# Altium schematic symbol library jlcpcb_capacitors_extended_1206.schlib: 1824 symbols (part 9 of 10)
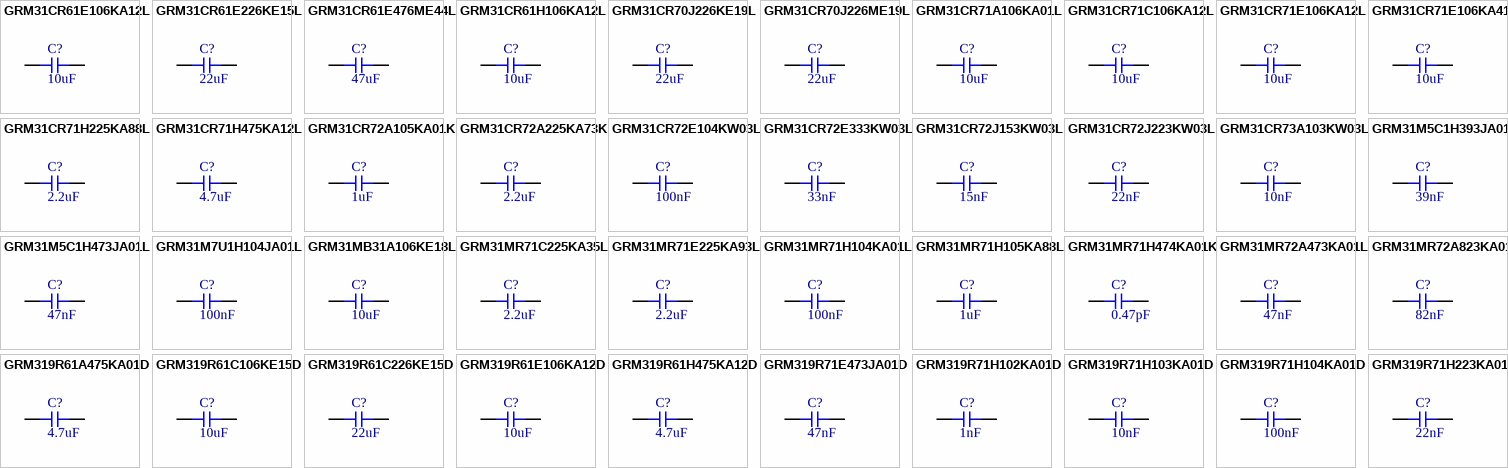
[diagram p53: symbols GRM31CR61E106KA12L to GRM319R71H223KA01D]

## GRM31CR72E333KW03L
designator C?  Capacitance: 33nF  (hidden comment: *)
Capacitor, Ceramic (MLCC), 33nF, ±10%, 250V, X7R, ±10%, SMD 1206; Manufacturer: Murata Electronics; Manufacturer Part Number: GRM31CR72E333KW03L
footprint CAP-1206 (1206 (3216M) Capacitor)
pins: 1, 2

## GRM31CR72J153KW03L
designator C?  Capacitance: 15nF  (hidden comment: *)
Capacitor, Ceramic (MLCC), 15nF, ±10%, 630V, X7R, ±10%, SMD 1206; Manufacturer: Murata Electronics; Manufacturer Part Number: GRM31CR72J153KW03L
footprint CAP-1206 (1206 (3216M) Capacitor)
pins: 1, 2

## GRM31CR72J223KW03L
designator C?  Capacitance: 22nF  (hidden comment: *)
Capacitor, Ceramic (MLCC), 22nF, ±10%, 630V, X7R, ±10%, SMD 1206; Manufacturer: Murata Electronics; Manufacturer Part Number: GRM31CR72J223KW03L
footprint CAP-1206 (1206 (3216M) Capacitor)
pins: 1, 2

## GRM31CR73A103KW03L
designator C?  Capacitance: 10nF  (hidden comment: *)
Capacitor, Ceramic (MLCC), 10nF, ±10%, 1kV, X7R, ±10%, SMD 1206; Manufacturer: Murata Electronics; Manufacturer Part Number: GRM31CR73A103KW03L
footprint CAP-1206 (1206 (3216M) Capacitor)
pins: 1, 2

## GRM31M5C1H393JA01L
designator C?  Capacitance: 39nF  (hidden comment: *)
Capacitor, Ceramic (MLCC), 39nF, ±5%, ±5%, SMD 1206; Manufacturer: Murata Electronics; Manufacturer Part Number: GRM31M5C1H393JA01L
footprint CAP-1206 (1206 (3216M) Capacitor)
pins: 1, 2

## GRM31M5C1H473JA01L
designator C?  Capacitance: 47nF  (hidden comment: *)
Capacitor, Ceramic (MLCC), 47nF, ±5%, 50V, C0G, ±5%, SMD 1206; Manufacturer: Murata Electronics; Manufacturer Part Number: GRM31M5C1H473JA01L
footprint CAP-1206 (1206 (3216M) Capacitor)
pins: 1, 2

## GRM31M7U1H104JA01L
designator C?  Capacitance: 100nF  (hidden comment: *)
Capacitor, Ceramic (MLCC), 100nF, ±5%, 50V, U2J, ±5%, SMD 1206; Manufacturer: Murata Electronics; Manufacturer Part Number: GRM31M7U1H104JA01L
footprint CAP-1206 (1206 (3216M) Capacitor)
pins: 1, 2

## GRM31MB31A106KE18L
designator C?  Capacitance: 10uF  (hidden comment: *)
Capacitor, Ceramic (MLCC), 10uF, ±10%, 10V, B, ±10%, SMD 1206; Manufacturer: Murata Electronics; Manufacturer Part Number: GRM31MB31A106KE18L
footprint CAP-1206 (1206 (3216M) Capacitor)
pins: 1, 2

## GRM31MR71C225KA35L
designator C?  Capacitance: 2.2uF  (hidden comment: *)
Capacitor, Ceramic (MLCC), 2.2uF, ±10%, 16V, X7R, ±10%, SMD 1206; Manufacturer: Murata Electronics; Manufacturer Part Number: GRM31MR71C225KA35L
footprint CAP-1206 (1206 (3216M) Capacitor)
pins: 1, 2

## GRM31MR71E225KA93L
designator C?  Capacitance: 2.2uF  (hidden comment: *)
Capacitor, Ceramic (MLCC), 2.2uF, ±10%, 25V, X7R, ±10%, SMD 1206; Manufacturer: Murata Electronics; Manufacturer Part Number: GRM31MR71E225KA93L
footprint CAP-1206 (1206 (3216M) Capacitor)
pins: 1, 2

## GRM31MR71H104KA01L
designator C?  Capacitance: 100nF  (hidden comment: *)
Capacitor, Ceramic (MLCC), 100nF, ±10%, ±10%, SMD 1206; Manufacturer: Murata Electronics; Manufacturer Part Number: GRM31MR71H104KA01L
footprint CAP-1206 (1206 (3216M) Capacitor)
pins: 1, 2

## GRM31MR71H105KA88L
designator C?  Capacitance: 1uF  (hidden comment: *)
Capacitor, Ceramic (MLCC), 1uF, ±10%, 50V, X7R, ±10%, SMD 1206; Manufacturer: Murata Electronics; Manufacturer Part Number: GRM31MR71H105KA88L
footprint CAP-1206 (1206 (3216M) Capacitor)
pins: 1, 2

## GRM31MR71H474KA01K
designator C?  Capacitance: 0.47pF  (hidden comment: *)
Capacitor, Ceramic (MLCC), 0.47pF, ±10%, 50V, X7R, ±10%, SMD 1206; Manufacturer: Murata Electronics; Manufacturer Part Number: GRM31MR71H474KA01K
footprint CAP-1206 (1206 (3216M) Capacitor)
pins: 1, 2

## GRM31MR72A473KA01L
designator C?  Capacitance: 47nF  (hidden comment: *)
Capacitor, Ceramic (MLCC), 47nF, ±10%, 100V, X7R, ±10%, SMD 1206; Manufacturer: Murata Electronics; Manufacturer Part Number: GRM31MR72A473KA01L
footprint CAP-1206 (1206 (3216M) Capacitor)
pins: 1, 2

## GRM31MR72A823KA01L
designator C?  Capacitance: 82nF  (hidden comment: *)
Capacitor, Ceramic (MLCC), 82nF, ±10%, 100V, X7R, ±10%, SMD 1206; Manufacturer: Murata Electronics; Manufacturer Part Number: GRM31MR72A823KA01L
footprint CAP-1206 (1206 (3216M) Capacitor)
pins: 1, 2

## GRM319R61A475KA01D
designator C?  Capacitance: 4.7uF  (hidden comment: *)
Capacitor, Ceramic (MLCC), 4.7uF, ±10%, 10V, X5R, ±10%, SMD 1206; Manufacturer: Murata Electronics; Manufacturer Part Number: GRM319R61A475KA01D
footprint CAP-1206 (1206 (3216M) Capacitor)
pins: 1, 2

## GRM319R61C106KE15D
designator C?  Capacitance: 10uF  (hidden comment: *)
Capacitor, Ceramic (MLCC), 10uF, ±10%, 16V, X5R, ±10%, SMD 1206; Manufacturer: Murata Electronics; Manufacturer Part Number: GRM319R61C106KE15D
footprint CAP-1206 (1206 (3216M) Capacitor)
pins: 1, 2

## GRM319R61C226KE15D
designator C?  Capacitance: 22uF  (hidden comment: *)
Capacitor, Ceramic (MLCC), 22uF, ±10%, 16V, X5R, ±10%, SMD 1206; Manufacturer: Murata Electronics; Manufacturer Part Number: GRM319R61C226KE15D
footprint CAP-1206 (1206 (3216M) Capacitor)
pins: 1, 2

## GRM319R61E106KA12D
designator C?  Capacitance: 10uF  (hidden comment: *)
Capacitor, Ceramic (MLCC), 10uF, ±10%, 25V, X5R, ±10%, SMD 1206; Manufacturer: Murata Electronics; Manufacturer Part Number: GRM319R61E106KA12D
footprint CAP-1206 (1206 (3216M) Capacitor)
pins: 1, 2

## GRM319R61H475KA12D
designator C?  Capacitance: 4.7uF  (hidden comment: *)
Capacitor, Ceramic (MLCC), 4.7uF, ±10%, 50V, X5R, ±10%, SMD 1206; Manufacturer: Murata Electronics; Manufacturer Part Number: GRM319R61H475KA12D
footprint CAP-1206 (1206 (3216M) Capacitor)
pins: 1, 2

## GRM319R71E473JA01D
designator C?  Capacitance: 47nF  (hidden comment: *)
Capacitor, Ceramic (MLCC), 47nF, ±5%, 25V, X7R, ±5%, SMD 1206; Manufacturer: Murata Electronics; Manufacturer Part Number: GRM319R71E473JA01D
footprint CAP-1206 (1206 (3216M) Capacitor)
pins: 1, 2

## GRM319R71H102KA01D
designator C?  Capacitance: 1nF  (hidden comment: *)
Capacitor, Ceramic (MLCC), 1nF, ±10%, 50V, X7R, ±10%, SMD 1206; Manufacturer: Murata Electronics; Manufacturer Part Number: GRM319R71H102KA01D
footprint CAP-1206 (1206 (3216M) Capacitor)
pins: 1, 2

## GRM319R71H103KA01D
designator C?  Capacitance: 10nF  (hidden comment: *)
Capacitor, Ceramic (MLCC), 10nF, ±10%, 50V, X7R, ±10%, SMD 1206; Manufacturer: Murata Electronics; Manufacturer Part Number: GRM319R71H103KA01D
footprint CAP-1206 (1206 (3216M) Capacitor)
pins: 1, 2

## GRM319R71H104KA01D
designator C?  Capacitance: 100nF  (hidden comment: *)
Capacitor, Ceramic (MLCC), 100nF, ±10%, 50V, X7R, ±10%, SMD 1206; Manufacturer: Murata Electronics; Manufacturer Part Number: GRM319R71H104KA01D
footprint CAP-1206 (1206 (3216M) Capacitor)
pins: 1, 2

## GRM319R71H223KA01D
designator C?  Capacitance: 22nF  (hidden comment: *)
Capacitor, Ceramic (MLCC), 22nF, ±10%, 50V, X7R, ±10%, SMD 1206; Manufacturer: Murata Electronics; Manufacturer Part Number: GRM319R71H223KA01D
footprint CAP-1206 (1206 (3216M) Capacitor)
pins: 1, 2

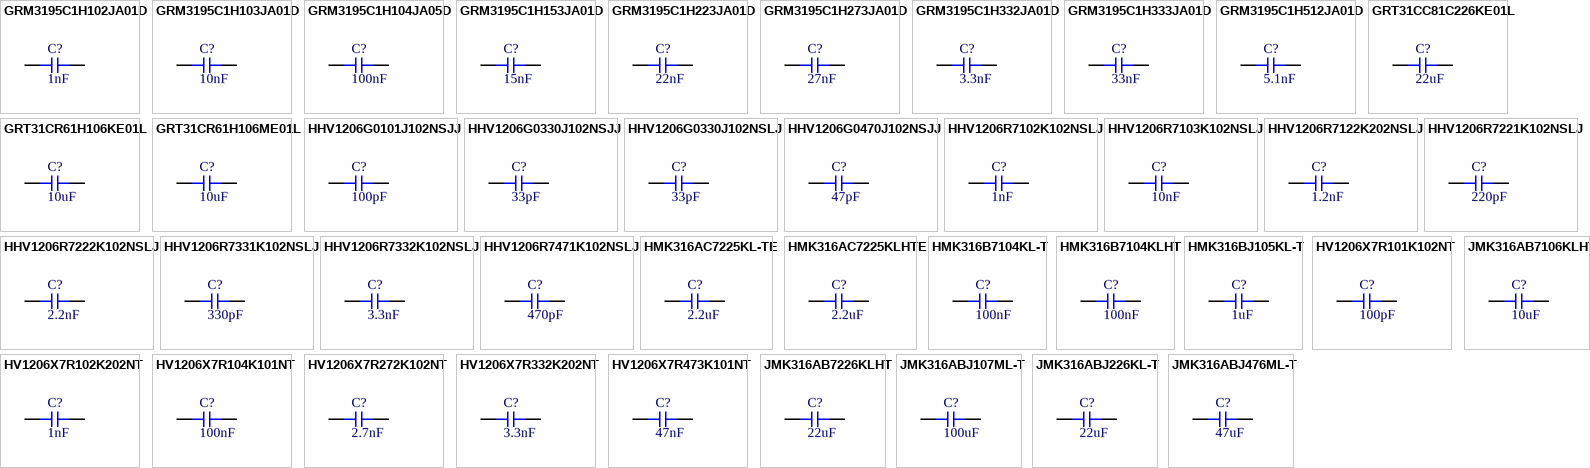
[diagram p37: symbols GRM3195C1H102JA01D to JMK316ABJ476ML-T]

## GRM3195C1H102JA01D
designator C?  Capacitance: 1nF  (hidden comment: *)
Capacitor, Ceramic (MLCC), 1nF, ±5%, 50V, C0G, ±5%, SMD 1206; Manufacturer: Murata Electronics; Manufacturer Part Number: GRM3195C1H102JA01D
footprint CAP-1206 (1206 (3216M) Capacitor)
pins: 1, 2

## GRM3195C1H103JA01D
designator C?  Capacitance: 10nF  (hidden comment: *)
Capacitor, Ceramic (MLCC), 10nF, ±5%, 50V, C0G, ±5%, SMD 1206; Manufacturer: Murata Electronics; Manufacturer Part Number: GRM3195C1H103JA01D
footprint CAP-1206 (1206 (3216M) Capacitor)
pins: 1, 2

## GRM3195C1H104JA05D
designator C?  Capacitance: 100nF  (hidden comment: *)
Capacitor, Ceramic (MLCC), 100nF, ±5%, 50V, C0G, ±5%, SMD 1206; Manufacturer: Murata Electronics; Manufacturer Part Number: GRM3195C1H104JA05D
footprint CAP-1206 (1206 (3216M) Capacitor)
pins: 1, 2

## GRM3195C1H153JA01D
designator C?  Capacitance: 15nF  (hidden comment: *)
Capacitor, Ceramic (MLCC), 15nF, ±5%, 50V, C0G, ±5%, SMD 1206; Manufacturer: Murata Electronics; Manufacturer Part Number: GRM3195C1H153JA01D
footprint CAP-1206 (1206 (3216M) Capacitor)
pins: 1, 2

## GRM3195C1H223JA01D
designator C?  Capacitance: 22nF  (hidden comment: *)
Capacitor, Ceramic (MLCC), 22nF, ±5%, 50V, C0G, ±5%, SMD 1206; Manufacturer: Murata Electronics; Manufacturer Part Number: GRM3195C1H223JA01D
footprint CAP-1206 (1206 (3216M) Capacitor)
pins: 1, 2

## GRM3195C1H273JA01D
designator C?  Capacitance: 27nF  (hidden comment: *)
Capacitor, Ceramic (MLCC), 27nF, ±5%, 50V, C0G, ±5%, SMD 1206; Manufacturer: Murata Electronics; Manufacturer Part Number: GRM3195C1H273JA01D
footprint CAP-1206 (1206 (3216M) Capacitor)
pins: 1, 2

## GRM3195C1H332JA01D
designator C?  Capacitance: 3.3nF  (hidden comment: *)
Capacitor, Ceramic (MLCC), 3.3nF, ±5%, 50V, C0G, ±5%, SMD 1206; Manufacturer: Murata Electronics; Manufacturer Part Number: GRM3195C1H332JA01D
footprint CAP-1206 (1206 (3216M) Capacitor)
pins: 1, 2

## GRM3195C1H333JA01D
designator C?  Capacitance: 33nF  (hidden comment: *)
Capacitor, Ceramic (MLCC), 33nF, ±5%, 50V, C0G, ±5%, SMD 1206; Manufacturer: Murata Electronics; Manufacturer Part Number: GRM3195C1H333JA01D
footprint CAP-1206 (1206 (3216M) Capacitor)
pins: 1, 2

## GRM3195C1H512JA01D
designator C?  Capacitance: 5.1nF  (hidden comment: *)
Capacitor, Ceramic (MLCC), 5.1nF, ±5%, 50V, C0G, ±5%, SMD 1206; Manufacturer: Murata Electronics; Manufacturer Part Number: GRM3195C1H512JA01D
footprint CAP-1206 (1206 (3216M) Capacitor)
pins: 1, 2

## GRT31CC81C226KE01L
designator C?  Capacitance: 22uF  (hidden comment: *)
Capacitor, Ceramic (MLCC), 22uF, ±10%, 16V, X6S, ±10%, SMD 1206; Manufacturer: Murata Electronics; Manufacturer Part Number: GRT31CC81C226KE01L
footprint CAP-1206 (1206 (3216M) Capacitor)
pins: 1, 2

## GRT31CR61H106KE01L
designator C?  Capacitance: 10uF  (hidden comment: *)
Capacitor, Ceramic (MLCC), 10uF, ±10%, 50V, X5R, ±10%, SMD 1206; Manufacturer: Murata Electronics; Manufacturer Part Number: GRT31CR61H106KE01L
footprint CAP-1206 (1206 (3216M) Capacitor)
pins: 1, 2

## GRT31CR61H106ME01L
designator C?  Capacitance: 10uF  (hidden comment: *)
Capacitor, Ceramic (MLCC), 10uF, ±20%, 50V, X5R, ±20%, SMD 1206; Manufacturer: Murata Electronics; Manufacturer Part Number: GRT31CR61H106ME01L
footprint CAP-1206 (1206 (3216M) Capacitor)
pins: 1, 2

## HHV1206G0101J102NSJJ
designator C?  Capacitance: 100pF  (hidden comment: *)
Capacitor, Ceramic (MLCC), 100pF, ±5%, 1kV, C0G, ±5%, SMD 1206; Manufacturer: Chinocera; Manufacturer Part Number: HHV1206G0101J102NSJJ
footprint CAP-1206 (1206 (3216M) Capacitor)
pins: 1, 2

## HHV1206G0330J102NSJJ
designator C?  Capacitance: 33pF  (hidden comment: *)
Capacitor, Ceramic (MLCC), 33pF, ±5%, 1kV, C0G, ±5%, SMD 1206; Manufacturer: Chinocera; Manufacturer Part Number: HHV1206G0330J102NSJJ
footprint CAP-1206 (1206 (3216M) Capacitor)
pins: 1, 2

## HHV1206G0330J102NSLJ
designator C?  Capacitance: 33pF  (hidden comment: *)
Capacitor, Ceramic (MLCC), 33pF, ±5%, 1kV, C0G, ±5%, SMD 1206; Manufacturer: Chinocera; Manufacturer Part Number: HHV1206G0330J102NSLJ
footprint CAP-1206 (1206 (3216M) Capacitor)
pins: 1, 2

## HHV1206G0470J102NSJJ
designator C?  Capacitance: 47pF  (hidden comment: *)
Capacitor, Ceramic (MLCC), 47pF, ±5%, 1kV, C0G, ±5%, SMD 1206; Manufacturer: Chinocera; Manufacturer Part Number: HHV1206G0470J102NSJJ
footprint CAP-1206 (1206 (3216M) Capacitor)
pins: 1, 2

## HHV1206R7102K102NSLJ
designator C?  Capacitance: 1nF  (hidden comment: *)
Capacitor, Ceramic (MLCC), 1nF, ±10%, 1kV, X7R, ±10%, SMD 1206; Manufacturer: Chinocera; Manufacturer Part Number: HHV1206R7102K102NSLJ
footprint CAP-1206 (1206 (3216M) Capacitor)
pins: 1, 2

## HHV1206R7103K102NSLJ
designator C?  Capacitance: 10nF  (hidden comment: *)
Capacitor, Ceramic (MLCC), 10nF, ±10%, 1kV, X7R, ±10%, SMD 1206; Manufacturer: Chinocera; Manufacturer Part Number: HHV1206R7103K102NSLJ
footprint CAP-1206 (1206 (3216M) Capacitor)
pins: 1, 2

## HHV1206R7122K202NSLJ
designator C?  Capacitance: 1.2nF  (hidden comment: *)
Capacitor, Ceramic (MLCC), 1.2nF, ±10%, 2kV, X7R, ±10%, SMD 1206; Manufacturer: Chinocera; Manufacturer Part Number: HHV1206R7122K202NSLJ
footprint CAP-1206 (1206 (3216M) Capacitor)
pins: 1, 2

## HHV1206R7221K102NSLJ
designator C?  Capacitance: 220pF  (hidden comment: *)
Capacitor, Ceramic (MLCC), 220pF, ±10%, 1kV, X7R, ±10%, SMD 1206; Manufacturer: Chinocera; Manufacturer Part Number: HHV1206R7221K102NSLJ
footprint CAP-1206 (1206 (3216M) Capacitor)
pins: 1, 2

## HHV1206R7222K102NSLJ
designator C?  Capacitance: 2.2nF  (hidden comment: *)
Capacitor, Ceramic (MLCC), 2.2nF, ±10%, 1kV, X7R, ±10%, SMD 1206; Manufacturer: Chinocera; Manufacturer Part Number: HHV1206R7222K102NSLJ
footprint CAP-1206 (1206 (3216M) Capacitor)
pins: 1, 2

## HHV1206R7331K102NSLJ
designator C?  Capacitance: 330pF  (hidden comment: *)
Capacitor, Ceramic (MLCC), 330pF, ±10%, 1kV, X7R, ±10%, SMD 1206; Manufacturer: Chinocera; Manufacturer Part Number: HHV1206R7331K102NSLJ
footprint CAP-1206 (1206 (3216M) Capacitor)
pins: 1, 2

## HHV1206R7332K102NSLJ
designator C?  Capacitance: 3.3nF  (hidden comment: *)
Capacitor, Ceramic (MLCC), 3.3nF, ±10%, 1kV, X7R, ±10%, SMD 1206; Manufacturer: Chinocera; Manufacturer Part Number: HHV1206R7332K102NSLJ
footprint CAP-1206 (1206 (3216M) Capacitor)
pins: 1, 2

## HHV1206R7471K102NSLJ
designator C?  Capacitance: 470pF  (hidden comment: *)
Capacitor, Ceramic (MLCC), 470pF, ±10%, 1kV, X7R, ±10%, SMD 1206; Manufacturer: Chinocera; Manufacturer Part Number: HHV1206R7471K102NSLJ
footprint CAP-1206 (1206 (3216M) Capacitor)
pins: 1, 2

## HMK316AC7225KL-TE
designator C?  Capacitance: 2.2uF  (hidden comment: *)
Capacitor, Ceramic (MLCC), 2.2uF, ±10%, 100V, ±10%, SMD 1206; Manufacturer: Taiyo Yuden; Manufacturer Part Number: HMK316AC7225KL-TE
footprint CAP-1206 (1206 (3216M) Capacitor)
pins: 1, 2

## HMK316AC7225KLHTE
designator C?  Capacitance: 2.2uF  (hidden comment: *)
Capacitor, Ceramic (MLCC), 2.2uF, ±10%, 100V, X7S, ±10%, SMD 1206; Manufacturer: Taiyo Yuden; Manufacturer Part Number: HMK316AC7225KLHTE
footprint CAP-1206 (1206 (3216M) Capacitor)
pins: 1, 2

## HMK316B7104KL-T
designator C?  Capacitance: 100nF  (hidden comment: *)
Capacitor, Ceramic (MLCC), 100nF, ±10%, 100V, X7R, ±10%, SMD 1206; Manufacturer: Taiyo Yuden; Manufacturer Part Number: HMK316B7104KL-T
footprint CAP-1206 (1206 (3216M) Capacitor)
pins: 1, 2

## HMK316B7104KLHT
designator C?  Capacitance: 100nF  (hidden comment: *)
Capacitor, Ceramic (MLCC), 100nF, ±10%, 100V, X7R, ±10%, SMD 1206; Manufacturer: Taiyo Yuden; Manufacturer Part Number: HMK316B7104KLHT
footprint CAP-1206 (1206 (3216M) Capacitor)
pins: 1, 2

## HMK316BJ105KL-T
designator C?  Capacitance: 1uF  (hidden comment: *)
Capacitor, Ceramic (MLCC), 1uF, ±10%, 100V, X5R, ±10%, SMD 1206; Manufacturer: Taiyo Yuden; Manufacturer Part Number: HMK316BJ105KL-T
footprint CAP-1206 (1206 (3216M) Capacitor)
pins: 1, 2

## HV1206X7R101K102NT
designator C?  Capacitance: 100pF  (hidden comment: *)
Capacitor, Ceramic (MLCC), 100pF, ±10%, 1kV, ±10%, SMD 1206; Manufacturer: AIDE; Manufacturer Part Number: HV1206X7R101K102NT
footprint CAP-1206 (1206 (3216M) Capacitor)
pins: 1, 2

## HV1206X7R102K202NT
designator C?  Capacitance: 1nF  (hidden comment: *)
Capacitor, Ceramic (MLCC), 1nF, ±10%, 2kV, ±10%, SMD 1206; Manufacturer: AIDE; Manufacturer Part Number: HV1206X7R102K202NT
footprint CAP-1206 (1206 (3216M) Capacitor)
pins: 1, 2

## HV1206X7R104K101NT
designator C?  Capacitance: 100nF  (hidden comment: *)
Capacitor, Ceramic (MLCC), 100nF, ±10%, 100V, ±10%, SMD 1206; Manufacturer: AIDE; Manufacturer Part Number: HV1206X7R104K101NT
footprint CAP-1206 (1206 (3216M) Capacitor)
pins: 1, 2

## HV1206X7R272K102NT
designator C?  Capacitance: 2.7nF  (hidden comment: *)
Capacitor, Ceramic (MLCC), 2.7nF, ±10%, 1kV, ±10%, SMD 1206; Manufacturer: AIDE; Manufacturer Part Number: HV1206X7R272K102NT
footprint CAP-1206 (1206 (3216M) Capacitor)
pins: 1, 2

## HV1206X7R332K202NT
designator C?  Capacitance: 3.3nF  (hidden comment: *)
Capacitor, Ceramic (MLCC), 3.3nF, ±10%, 2kV, ±10%, SMD 1206; Manufacturer: AIDE; Manufacturer Part Number: HV1206X7R332K202NT
footprint CAP-1206 (1206 (3216M) Capacitor)
pins: 1, 2

## HV1206X7R473K101NT
designator C?  Capacitance: 47nF  (hidden comment: *)
Capacitor, Ceramic (MLCC), 47nF, ±10%, 100V, ±10%, SMD 1206; Manufacturer: AIDE; Manufacturer Part Number: HV1206X7R473K101NT
footprint CAP-1206 (1206 (3216M) Capacitor)
pins: 1, 2

## JMK316AB7106KLHT
designator C?  Capacitance: 10uF  (hidden comment: *)
Capacitor, Ceramic (MLCC), 10uF, ±10%, 6.3V, ±10%, SMD 1206; Manufacturer: Taiyo Yuden; Manufacturer Part Number: JMK316AB7106KLHT
footprint CAP-1206 (1206 (3216M) Capacitor)
pins: 1, 2

## JMK316AB7226KLHT
designator C?  Capacitance: 22uF  (hidden comment: *)
Capacitor, Ceramic (MLCC), 22uF, ±10%, 6.3V, X7R, ±10%, SMD 1206; Manufacturer: Taiyo Yuden; Manufacturer Part Number: JMK316AB7226KLHT
footprint CAP-1206 (1206 (3216M) Capacitor)
pins: 1, 2

## JMK316ABJ107ML-T
designator C?  Capacitance: 100uF  (hidden comment: *)
Capacitor, Ceramic (MLCC), 100uF, ±20%, 6.3V, X5R, ±20%, SMD 1206; Manufacturer: Taiyo Yuden; Manufacturer Part Number: JMK316ABJ107ML-T
footprint CAP-1206 (1206 (3216M) Capacitor)
pins: 1, 2

## JMK316ABJ226KL-T
designator C?  Capacitance: 22uF  (hidden comment: *)
Capacitor, Ceramic (MLCC), 22uF, ±10%, 6.3V, ±10%, SMD 1206; Manufacturer: Taiyo Yuden; Manufacturer Part Number: JMK316ABJ226KL-T
footprint CAP-1206 (1206 (3216M) Capacitor)
pins: 1, 2

## JMK316ABJ476ML-T
designator C?  Capacitance: 47uF  (hidden comment: *)
Capacitor, Ceramic (MLCC), 47uF, ±20%, 6.3V, X5R, ±20%, SMD 1206; Manufacturer: Taiyo Yuden; Manufacturer Part Number: JMK316ABJ476ML-T
footprint CAP-1206 (1206 (3216M) Capacitor)
pins: 1, 2

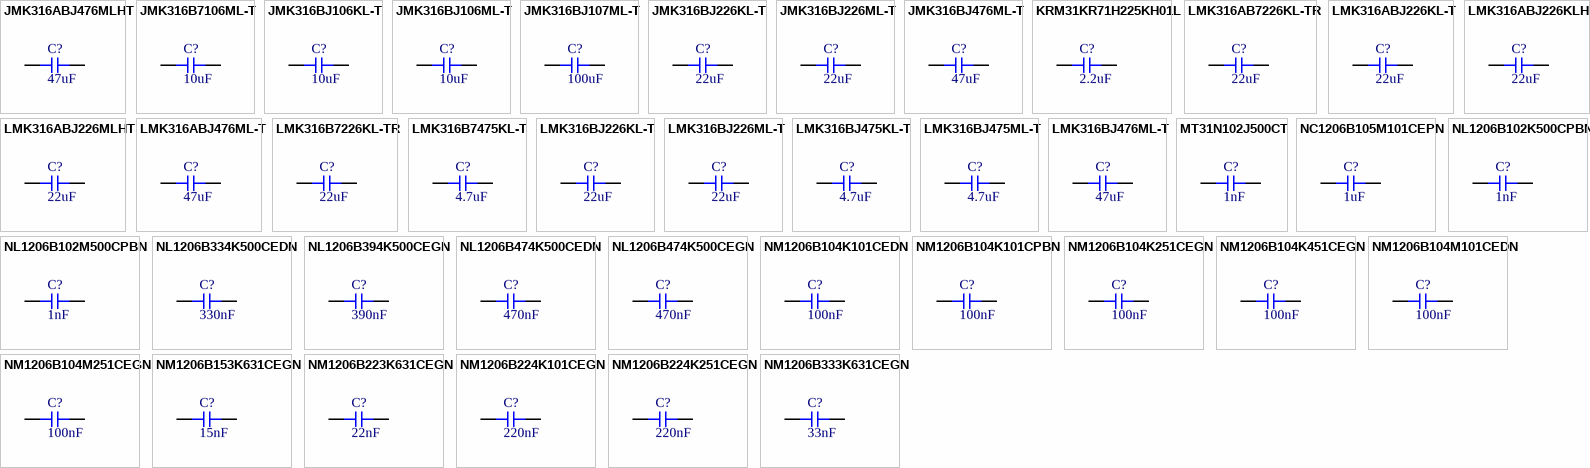
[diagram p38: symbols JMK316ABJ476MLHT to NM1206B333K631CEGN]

## JMK316ABJ476MLHT
designator C?  Capacitance: 47uF  (hidden comment: *)
Capacitor, Ceramic (MLCC), 47uF, ±20%, 6.3V, X5R, ±20%, SMD 1206; Manufacturer: Taiyo Yuden; Manufacturer Part Number: JMK316ABJ476MLHT
footprint CAP-1206 (1206 (3216M) Capacitor)
pins: 1, 2

## JMK316B7106ML-T
designator C?  Capacitance: 10uF  (hidden comment: *)
Capacitor, Ceramic (MLCC), 10uF, ±20%, 6.3V, X7R, ±20%, SMD 1206; Manufacturer: Taiyo Yuden; Manufacturer Part Number: JMK316B7106ML-T
footprint CAP-1206 (1206 (3216M) Capacitor)
pins: 1, 2

## JMK316BJ106KL-T
designator C?  Capacitance: 10uF  (hidden comment: *)
Capacitor, Ceramic (MLCC), 10uF, ±10%, 6.3V, X5R, ±10%, SMD 1206; Manufacturer: Taiyo Yuden; Manufacturer Part Number: JMK316BJ106KL-T
footprint CAP-1206 (1206 (3216M) Capacitor)
pins: 1, 2

## JMK316BJ106ML-T
designator C?  Capacitance: 10uF  (hidden comment: *)
Capacitor, Ceramic (MLCC), 10uF, ±20%, 6.3V, X5R, ±20%, SMD 1206; Manufacturer: Taiyo Yuden; Manufacturer Part Number: JMK316BJ106ML-T
footprint CAP-1206 (1206 (3216M) Capacitor)
pins: 1, 2

## JMK316BJ107ML-T
designator C?  Capacitance: 100uF  (hidden comment: *)
Capacitor, Ceramic (MLCC), 100uF, ±20%, 6.3V, X5R, ±20%, SMD 1206; Manufacturer: Taiyo Yuden; Manufacturer Part Number: JMK316BJ107ML-T
footprint CAP-1206 (1206 (3216M) Capacitor)
pins: 1, 2

## JMK316BJ226KL-T
designator C?  Capacitance: 22uF  (hidden comment: *)
Capacitor, Ceramic (MLCC), 22uF, ±10%, 6.3V, X5R, ±10%, SMD 1206; Manufacturer: Taiyo Yuden; Manufacturer Part Number: JMK316BJ226KL-T
footprint CAP-1206 (1206 (3216M) Capacitor)
pins: 1, 2

## JMK316BJ226ML-T
designator C?  Capacitance: 22uF  (hidden comment: *)
Capacitor, Ceramic (MLCC), 22uF, ±20%, 6.3V, X5R, ±20%, SMD 1206; Manufacturer: Taiyo Yuden; Manufacturer Part Number: JMK316BJ226ML-T
footprint CAP-1206 (1206 (3216M) Capacitor)
pins: 1, 2

## JMK316BJ476ML-T
designator C?  Capacitance: 47uF  (hidden comment: *)
Capacitor, Ceramic (MLCC), 47uF, ±20%, 6.3V, X5R, ±20%, SMD 1206; Manufacturer: Taiyo Yuden; Manufacturer Part Number: JMK316BJ476ML-T
footprint CAP-1206 (1206 (3216M) Capacitor)
pins: 1, 2

## KRM31KR71H225KH01L
designator C?  Capacitance: 2.2uF  (hidden comment: *)
Capacitor, Ceramic (MLCC), 2.2uF, ±10%, 50V, X7R, ±10%, SMD 1206; Manufacturer: Murata Electronics; Manufacturer Part Number: KRM31KR71H225KH01L
footprint CAP-1206 (1206 (3216M) Capacitor)
pins: 1, 2

## LMK316AB7226KL-TR
designator C?  Capacitance: 22uF  (hidden comment: *)
Capacitor, Ceramic (MLCC), 22uF, ±10%, 10V, X7R, ±10%, SMD 1206; Manufacturer: Taiyo Yuden; Manufacturer Part Number: LMK316AB7226KL-TR
footprint CAP-1206 (1206 (3216M) Capacitor)
pins: 1, 2

## LMK316ABJ226KL-T
designator C?  Capacitance: 22uF  (hidden comment: *)
Capacitor, Ceramic (MLCC), 22uF, ±10%, 10V, X5R, ±10%, SMD 1206; Manufacturer: Taiyo Yuden; Manufacturer Part Number: LMK316ABJ226KL-T
footprint CAP-1206 (1206 (3216M) Capacitor)
pins: 1, 2

## LMK316ABJ226KLHT
designator C?  Capacitance: 22uF  (hidden comment: *)
Capacitor, Ceramic (MLCC), 22uF, ±10%, 10V, X5R, ±10%, SMD 1206; Manufacturer: Taiyo Yuden; Manufacturer Part Number: LMK316ABJ226KLHT
footprint CAP-1206 (1206 (3216M) Capacitor)
pins: 1, 2

## LMK316ABJ226MLHT
designator C?  Capacitance: 22uF  (hidden comment: *)
Capacitor, Ceramic (MLCC), 22uF, ±20%, 10V, X5R, ±20%, SMD 1206; Manufacturer: Taiyo Yuden; Manufacturer Part Number: LMK316ABJ226MLHT
footprint CAP-1206 (1206 (3216M) Capacitor)
pins: 1, 2

## LMK316ABJ476ML-T
designator C?  Capacitance: 47uF  (hidden comment: *)
Capacitor, Ceramic (MLCC), 47uF, ±20%, 10V, X5R, ±20%, SMD 1206; Manufacturer: Taiyo Yuden; Manufacturer Part Number: LMK316ABJ476ML-T
footprint CAP-1206 (1206 (3216M) Capacitor)
pins: 1, 2

## LMK316B7226KL-TR
designator C?  Capacitance: 22uF  (hidden comment: *)
Capacitor, Ceramic (MLCC), 22uF, ±10%, 10V, X7R, ±10%, SMD 1206; Manufacturer: Taiyo Yuden; Manufacturer Part Number: LMK316B7226KL-TR
footprint CAP-1206 (1206 (3216M) Capacitor)
pins: 1, 2

## LMK316B7475KL-T
designator C?  Capacitance: 4.7uF  (hidden comment: *)
Capacitor, Ceramic (MLCC), 4.7uF, ±10%, 10V, X7R, ±10%, SMD 1206; Manufacturer: Taiyo Yuden; Manufacturer Part Number: LMK316B7475KL-T
footprint CAP-1206 (1206 (3216M) Capacitor)
pins: 1, 2

## LMK316BJ226KL-T
designator C?  Capacitance: 22uF  (hidden comment: *)
Capacitor, Ceramic (MLCC), 22uF, ±10%, 10V, X5R, ±10%, SMD 1206; Manufacturer: Taiyo Yuden; Manufacturer Part Number: LMK316BJ226KL-T
footprint CAP-1206 (1206 (3216M) Capacitor)
pins: 1, 2

## LMK316BJ226ML-T
designator C?  Capacitance: 22uF  (hidden comment: *)
Capacitor, Ceramic (MLCC), 22uF, ±20%, 10V, X5R, ±20%, SMD 1206; Manufacturer: Taiyo Yuden; Manufacturer Part Number: LMK316BJ226ML-T
footprint CAP-1206 (1206 (3216M) Capacitor)
pins: 1, 2

## LMK316BJ475KL-T
designator C?  Capacitance: 4.7uF  (hidden comment: *)
Capacitor, Ceramic (MLCC), 4.7uF, ±10%, 10V, X5R, ±10%, SMD 1206; Manufacturer: Taiyo Yuden; Manufacturer Part Number: LMK316BJ475KL-T
footprint CAP-1206 (1206 (3216M) Capacitor)
pins: 1, 2

## LMK316BJ475ML-T
designator C?  Capacitance: 4.7uF  (hidden comment: *)
Capacitor, Ceramic (MLCC), 4.7uF, ±20%, 10V, X5R, ±20%, SMD 1206; Manufacturer: Taiyo Yuden; Manufacturer Part Number: LMK316BJ475ML-T
footprint CAP-1206 (1206 (3216M) Capacitor)
pins: 1, 2

## LMK316BJ476ML-T
designator C?  Capacitance: 47uF  (hidden comment: *)
Capacitor, Ceramic (MLCC), 47uF, ±20%, 10V, X5R, ±20%, SMD 1206; Manufacturer: Taiyo Yuden; Manufacturer Part Number: LMK316BJ476ML-T
footprint CAP-1206 (1206 (3216M) Capacitor)
pins: 1, 2

## MT31N102J500CT
designator C?  Capacitance: 1nF  (hidden comment: *)
Capacitor, Ceramic (MLCC), 1nF, ±5%, 50V, NP0, ±5%, SMD 1206; Manufacturer: Walsin Tech Corp; Manufacturer Part Number: MT31N102J500CT
footprint CAP-1206 (1206 (3216M) Capacitor)
pins: 1, 2

## NC1206B105M101CEPN
designator C?  Capacitance: 1uF  (hidden comment: *)
Capacitor, Ceramic (MLCC), 1uF, ±20%, 100V, X7R, ±20%, SMD 1206; Manufacturer: HUI JU; Manufacturer Part Number: NC1206B105M101CEPN
footprint CAP-1206 (1206 (3216M) Capacitor)
pins: 1, 2

## NL1206B102K500CPBN
designator C?  Capacitance: 1nF  (hidden comment: *)
Capacitor, Ceramic (MLCC), 1nF, ±10%, 50V, ±10%, SMD 1206; Manufacturer: HUI JU; Manufacturer Part Number: NL1206B102K500CPBN
footprint CAP-1206 (1206 (3216M) Capacitor)
pins: 1, 2

## NL1206B102M500CPBN
designator C?  Capacitance: 1nF  (hidden comment: *)
Capacitor, Ceramic (MLCC), 1nF, ±20%, 50V, X7R, ±20%, SMD 1206; Manufacturer: HUI JU; Manufacturer Part Number: NL1206B102M500CPBN
footprint CAP-1206 (1206 (3216M) Capacitor)
pins: 1, 2

## NL1206B334K500CEDN
designator C?  Capacitance: 330nF  (hidden comment: *)
Capacitor, Ceramic (MLCC), 330nF, ±10%, 50V, X7R, ±10%, SMD 1206; Manufacturer: HUI JU; Manufacturer Part Number: NL1206B334K500CEDN
footprint CAP-1206 (1206 (3216M) Capacitor)
pins: 1, 2

## NL1206B394K500CEGN
designator C?  Capacitance: 390nF  (hidden comment: *)
Capacitor, Ceramic (MLCC), 390nF, ±10%, 50V, X7R, ±10%, SMD 1206; Manufacturer: HUI JU; Manufacturer Part Number: NL1206B394K500CEGN
footprint CAP-1206 (1206 (3216M) Capacitor)
pins: 1, 2

## NL1206B474K500CEDN
designator C?  Capacitance: 470nF  (hidden comment: *)
Capacitor, Ceramic (MLCC), 470nF, ±10%, 50V, X7R, ±10%, SMD 1206; Manufacturer: HUI JU; Manufacturer Part Number: NL1206B474K500CEDN
footprint CAP-1206 (1206 (3216M) Capacitor)
pins: 1, 2

## NL1206B474K500CEGN
designator C?  Capacitance: 470nF  (hidden comment: *)
Capacitor, Ceramic (MLCC), 470nF, ±10%, 50V, X7R, ±10%, SMD 1206; Manufacturer: HUI JU; Manufacturer Part Number: NL1206B474K500CEGN
footprint CAP-1206 (1206 (3216M) Capacitor)
pins: 1, 2

## NM1206B104K101CEDN
designator C?  Capacitance: 100nF  (hidden comment: *)
Capacitor, Ceramic (MLCC), 100nF, ±10%, 100V, X7R, ±10%, SMD 1206; Manufacturer: HUI JU; Manufacturer Part Number: NM1206B104K101CEDN
footprint CAP-1206 (1206 (3216M) Capacitor)
pins: 1, 2

## NM1206B104K101CPBN
designator C?  Capacitance: 100nF  (hidden comment: *)
Capacitor, Ceramic (MLCC), 100nF, ±10%, 100V, ±10%, SMD 1206; Manufacturer: HUI JU; Manufacturer Part Number: NM1206B104K101CPBN
footprint CAP-1206 (1206 (3216M) Capacitor)
pins: 1, 2

## NM1206B104K251CEGN
designator C?  Capacitance: 100nF  (hidden comment: *)
Capacitor, Ceramic (MLCC), 100nF, ±10%, 250V, X7R, ±10%, SMD 1206; Manufacturer: HUI JU; Manufacturer Part Number: NM1206B104K251CEGN
footprint CAP-1206 (1206 (3216M) Capacitor)
pins: 1, 2

## NM1206B104K451CEGN
designator C?  Capacitance: 100nF  (hidden comment: *)
Capacitor, Ceramic (MLCC), 100nF, ±10%, 450V, X7R, ±10%, SMD 1206; Manufacturer: HUI JU; Manufacturer Part Number: NM1206B104K451CEGN
footprint CAP-1206 (1206 (3216M) Capacitor)
pins: 1, 2

## NM1206B104M101CEDN
designator C?  Capacitance: 100nF  (hidden comment: *)
Capacitor, Ceramic (MLCC), 100nF, ±20%, 100V, X7R, ±20%, SMD 1206; Manufacturer: HUI JU; Manufacturer Part Number: NM1206B104M101CEDN
footprint CAP-1206 (1206 (3216M) Capacitor)
pins: 1, 2

## NM1206B104M251CEGN
designator C?  Capacitance: 100nF  (hidden comment: *)
Capacitor, Ceramic (MLCC), 100nF, ±20%, 250V, X7R, ±20%, SMD 1206; Manufacturer: HUI JU; Manufacturer Part Number: NM1206B104M251CEGN
footprint CAP-1206 (1206 (3216M) Capacitor)
pins: 1, 2

## NM1206B153K631CEGN
designator C?  Capacitance: 15nF  (hidden comment: *)
Capacitor, Ceramic (MLCC), 15nF, ±10%, 630V, X7R, ±10%, SMD 1206; Manufacturer: HUI JU; Manufacturer Part Number: NM1206B153K631CEGN
footprint CAP-1206 (1206 (3216M) Capacitor)
pins: 1, 2

## NM1206B223K631CEGN
designator C?  Capacitance: 22nF  (hidden comment: *)
Capacitor, Ceramic (MLCC), 22nF, ±10%, 630V, X7R, ±10%, SMD 1206; Manufacturer: HUI JU; Manufacturer Part Number: NM1206B223K631CEGN
footprint CAP-1206 (1206 (3216M) Capacitor)
pins: 1, 2

## NM1206B224K101CEGN
designator C?  Capacitance: 220nF  (hidden comment: *)
Capacitor, Ceramic (MLCC), 220nF, ±10%, 100V, X7R, ±10%, SMD 1206; Manufacturer: HUI JU; Manufacturer Part Number: NM1206B224K101CEGN
footprint CAP-1206 (1206 (3216M) Capacitor)
pins: 1, 2

## NM1206B224K251CEGN
designator C?  Capacitance: 220nF  (hidden comment: *)
Capacitor, Ceramic (MLCC), 220nF, ±10%, 250V, X7R, ±10%, SMD 1206; Manufacturer: HUI JU; Manufacturer Part Number: NM1206B224K251CEGN
footprint CAP-1206 (1206 (3216M) Capacitor)
pins: 1, 2

## NM1206B333K631CEGN
designator C?  Capacitance: 33nF  (hidden comment: *)
Capacitor, Ceramic (MLCC), 33nF, ±10%, 630V, X7R, ±10%, SMD 1206; Manufacturer: HUI JU; Manufacturer Part Number: NM1206B333K631CEGN
footprint CAP-1206 (1206 (3216M) Capacitor)
pins: 1, 2

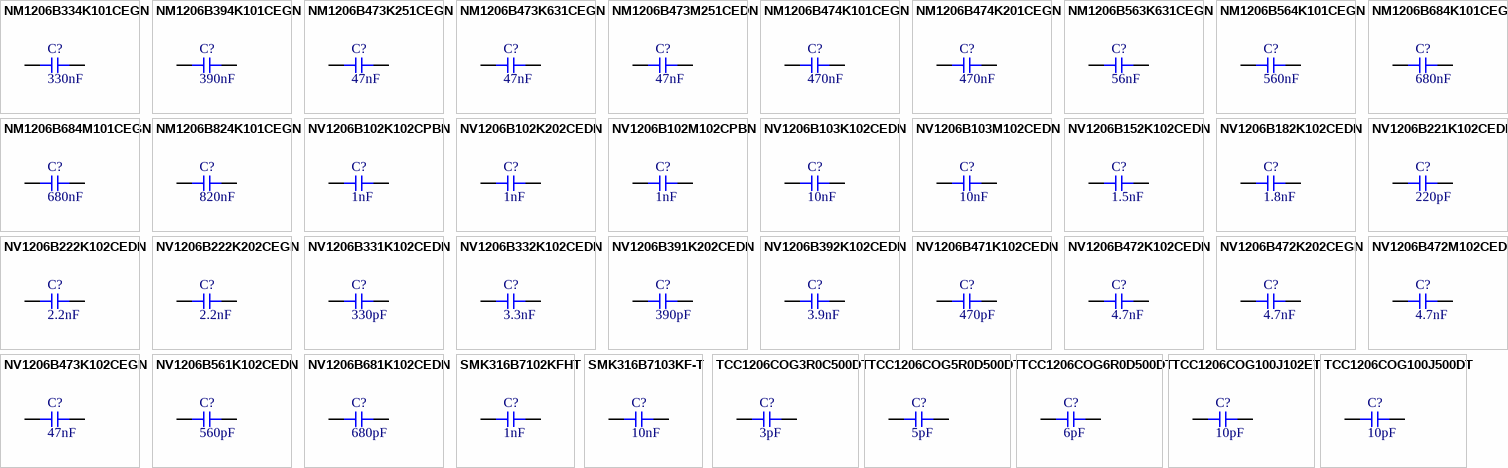
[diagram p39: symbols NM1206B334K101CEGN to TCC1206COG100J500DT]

## NM1206B334K101CEGN
designator C?  Capacitance: 330nF  (hidden comment: *)
Capacitor, Ceramic (MLCC), 330nF, ±10%, 100V, X7R, ±10%, SMD 1206; Manufacturer: HUI JU; Manufacturer Part Number: NM1206B334K101CEGN
footprint CAP-1206 (1206 (3216M) Capacitor)
pins: 1, 2

## NM1206B394K101CEGN
designator C?  Capacitance: 390nF  (hidden comment: *)
Capacitor, Ceramic (MLCC), 390nF, ±10%, 100V, X7R, ±10%, SMD 1206; Manufacturer: HUI JU; Manufacturer Part Number: NM1206B394K101CEGN
footprint CAP-1206 (1206 (3216M) Capacitor)
pins: 1, 2

## NM1206B473K251CEGN
designator C?  Capacitance: 47nF  (hidden comment: *)
Capacitor, Ceramic (MLCC), 47nF, ±10%, 250V, X7R, ±10%, SMD 1206; Manufacturer: HUI JU; Manufacturer Part Number: NM1206B473K251CEGN
footprint CAP-1206 (1206 (3216M) Capacitor)
pins: 1, 2

## NM1206B473K631CEGN
designator C?  Capacitance: 47nF  (hidden comment: *)
Capacitor, Ceramic (MLCC), 47nF, ±10%, 630V, X7R, ±10%, SMD 1206; Manufacturer: HUI JU; Manufacturer Part Number: NM1206B473K631CEGN
footprint CAP-1206 (1206 (3216M) Capacitor)
pins: 1, 2

## NM1206B473M251CEDN
designator C?  Capacitance: 47nF  (hidden comment: *)
Capacitor, Ceramic (MLCC), 47nF, ±20%, 250V, X7R, ±20%, SMD 1206; Manufacturer: HUI JU; Manufacturer Part Number: NM1206B473M251CEDN
footprint CAP-1206 (1206 (3216M) Capacitor)
pins: 1, 2

## NM1206B474K101CEGN
designator C?  Capacitance: 470nF  (hidden comment: *)
Capacitor, Ceramic (MLCC), 470nF, ±10%, 100V, X7R, ±10%, SMD 1206; Manufacturer: HUI JU; Manufacturer Part Number: NM1206B474K101CEGN
footprint CAP-1206 (1206 (3216M) Capacitor)
pins: 1, 2

## NM1206B474K201CEGN
designator C?  Capacitance: 470nF  (hidden comment: *)
Capacitor, Ceramic (MLCC), 470nF, ±10%, 200V, X7R, ±10%, SMD 1206; Manufacturer: HUI JU; Manufacturer Part Number: NM1206B474K201CEGN
footprint CAP-1206 (1206 (3216M) Capacitor)
pins: 1, 2

## NM1206B563K631CEGN
designator C?  Capacitance: 56nF  (hidden comment: *)
Capacitor, Ceramic (MLCC), 56nF, ±10%, 630V, X7R, ±10%, SMD 1206; Manufacturer: HUI JU; Manufacturer Part Number: NM1206B563K631CEGN
footprint CAP-1206 (1206 (3216M) Capacitor)
pins: 1, 2

## NM1206B564K101CEGN
designator C?  Capacitance: 560nF  (hidden comment: *)
Capacitor, Ceramic (MLCC), 560nF, ±10%, 100V, X7R, ±10%, SMD 1206; Manufacturer: HUI JU; Manufacturer Part Number: NM1206B564K101CEGN
footprint CAP-1206 (1206 (3216M) Capacitor)
pins: 1, 2

## NM1206B684K101CEGN
designator C?  Capacitance: 680nF  (hidden comment: *)
Capacitor, Ceramic (MLCC), 680nF, ±10%, 100V, X7R, ±10%, SMD 1206; Manufacturer: HUI JU; Manufacturer Part Number: NM1206B684K101CEGN
footprint CAP-1206 (1206 (3216M) Capacitor)
pins: 1, 2

## NM1206B684M101CEGN
designator C?  Capacitance: 680nF  (hidden comment: *)
Capacitor, Ceramic (MLCC), 680nF, ±20%, 100V, X7R, ±20%, SMD 1206; Manufacturer: HUI JU; Manufacturer Part Number: NM1206B684M101CEGN
footprint CAP-1206 (1206 (3216M) Capacitor)
pins: 1, 2

## NM1206B824K101CEGN
designator C?  Capacitance: 820nF  (hidden comment: *)
Capacitor, Ceramic (MLCC), 820nF, ±10%, 100V, X7R, ±10%, SMD 1206; Manufacturer: HUI JU; Manufacturer Part Number: NM1206B824K101CEGN
footprint CAP-1206 (1206 (3216M) Capacitor)
pins: 1, 2

## NV1206B102K102CPBN
designator C?  Capacitance: 1nF  (hidden comment: *)
Capacitor, Ceramic (MLCC), 1nF, ±10%, 1kV, ±10%, SMD 1206; Manufacturer: HUI JU; Manufacturer Part Number: NV1206B102K102CPBN
footprint CAP-1206 (1206 (3216M) Capacitor)
pins: 1, 2

## NV1206B102K202CEDN
designator C?  Capacitance: 1nF  (hidden comment: *)
Capacitor, Ceramic (MLCC), 1nF, ±10%, 2kV, X7R, ±10%, SMD 1206; Manufacturer: HUI JU; Manufacturer Part Number: NV1206B102K202CEDN
footprint CAP-1206 (1206 (3216M) Capacitor)
pins: 1, 2

## NV1206B102M102CPBN
designator C?  Capacitance: 1nF  (hidden comment: *)
Capacitor, Ceramic (MLCC), 1nF, ±20%, 1kV, ±20%, SMD 1206; Manufacturer: HUI JU; Manufacturer Part Number: NV1206B102M102CPBN
footprint CAP-1206 (1206 (3216M) Capacitor)
pins: 1, 2

## NV1206B103K102CEDN
designator C?  Capacitance: 10nF  (hidden comment: *)
Capacitor, Ceramic (MLCC), 10nF, ±10%, 1kV, X7R, ±10%, SMD 1206; Manufacturer: HUI JU; Manufacturer Part Number: NV1206B103K102CEDN
footprint CAP-1206 (1206 (3216M) Capacitor)
pins: 1, 2

## NV1206B103M102CEDN
designator C?  Capacitance: 10nF  (hidden comment: *)
Capacitor, Ceramic (MLCC), 10nF, ±20%, 1kV, X7R, ±20%, SMD 1206; Manufacturer: HUI JU; Manufacturer Part Number: NV1206B103M102CEDN
footprint CAP-1206 (1206 (3216M) Capacitor)
pins: 1, 2

## NV1206B152K102CEDN
designator C?  Capacitance: 1.5nF  (hidden comment: *)
Capacitor, Ceramic (MLCC), 1.5nF, ±10%, 1kV, X7R, ±10%, SMD 1206; Manufacturer: HUI JU; Manufacturer Part Number: NV1206B152K102CEDN
footprint CAP-1206 (1206 (3216M) Capacitor)
pins: 1, 2

## NV1206B182K102CEDN
designator C?  Capacitance: 1.8nF  (hidden comment: *)
Capacitor, Ceramic (MLCC), 1.8nF, ±10%, 1kV, ±10%, SMD 1206; Manufacturer: HUI JU; Manufacturer Part Number: NV1206B182K102CEDN
footprint CAP-1206 (1206 (3216M) Capacitor)
pins: 1, 2

## NV1206B221K102CEDN
designator C?  Capacitance: 220pF  (hidden comment: *)
Capacitor, Ceramic (MLCC), 220pF, ±10%, 1kV, X7R, ±10%, SMD 1206; Manufacturer: HUI JU; Manufacturer Part Number: NV1206B221K102CEDN
footprint CAP-1206 (1206 (3216M) Capacitor)
pins: 1, 2

## NV1206B222K102CEDN
designator C?  Capacitance: 2.2nF  (hidden comment: *)
Capacitor, Ceramic (MLCC), 2.2nF, ±10%, 1kV, X7R, ±10%, SMD 1206; Manufacturer: HUI JU; Manufacturer Part Number: NV1206B222K102CEDN
footprint CAP-1206 (1206 (3216M) Capacitor)
pins: 1, 2

## NV1206B222K202CEGN
designator C?  Capacitance: 2.2nF  (hidden comment: *)
Capacitor, Ceramic (MLCC), 2.2nF, ±10%, 2kV, X7R, ±10%, SMD 1206; Manufacturer: HUI JU; Manufacturer Part Number: NV1206B222K202CEGN
footprint CAP-1206 (1206 (3216M) Capacitor)
pins: 1, 2

## NV1206B331K102CEDN
designator C?  Capacitance: 330pF  (hidden comment: *)
Capacitor, Ceramic (MLCC), 330pF, ±10%, 1kV, X7R, ±10%, SMD 1206; Manufacturer: HUI JU; Manufacturer Part Number: NV1206B331K102CEDN
footprint CAP-1206 (1206 (3216M) Capacitor)
pins: 1, 2

## NV1206B332K102CEDN
designator C?  Capacitance: 3.3nF  (hidden comment: *)
Capacitor, Ceramic (MLCC), 3.3nF, ±10%, 1kV, X7R, ±10%, SMD 1206; Manufacturer: HUI JU; Manufacturer Part Number: NV1206B332K102CEDN
footprint CAP-1206 (1206 (3216M) Capacitor)
pins: 1, 2

## NV1206B391K202CEDN
designator C?  Capacitance: 390pF  (hidden comment: *)
Capacitor, Ceramic (MLCC), 390pF, ±10%, 2kV, X7R, ±10%, SMD 1206; Manufacturer: HUI JU; Manufacturer Part Number: NV1206B391K202CEDN
footprint CAP-1206 (1206 (3216M) Capacitor)
pins: 1, 2

## NV1206B392K102CEDN
designator C?  Capacitance: 3.9nF  (hidden comment: *)
Capacitor, Ceramic (MLCC), 3.9nF, ±10%, 1kV, ±10%, SMD 1206; Manufacturer: HUI JU; Manufacturer Part Number: NV1206B392K102CEDN
footprint CAP-1206 (1206 (3216M) Capacitor)
pins: 1, 2

## NV1206B471K102CEDN
designator C?  Capacitance: 470pF  (hidden comment: *)
Capacitor, Ceramic (MLCC), 470pF, ±10%, 1kV, X7R, ±10%, SMD 1206; Manufacturer: HUI JU; Manufacturer Part Number: NV1206B471K102CEDN
footprint CAP-1206 (1206 (3216M) Capacitor)
pins: 1, 2

## NV1206B472K102CEDN
designator C?  Capacitance: 4.7nF  (hidden comment: *)
Capacitor, Ceramic (MLCC), 4.7nF, ±10%, 1kV, X7R, ±10%, SMD 1206; Manufacturer: HUI JU; Manufacturer Part Number: NV1206B472K102CEDN
footprint CAP-1206 (1206 (3216M) Capacitor)
pins: 1, 2

## NV1206B472K202CEGN
designator C?  Capacitance: 4.7nF  (hidden comment: *)
Capacitor, Ceramic (MLCC), 4.7nF, ±10%, 2kV, X7R, ±10%, SMD 1206; Manufacturer: HUI JU; Manufacturer Part Number: NV1206B472K202CEGN
footprint CAP-1206 (1206 (3216M) Capacitor)
pins: 1, 2

## NV1206B472M102CEDN
designator C?  Capacitance: 4.7nF  (hidden comment: *)
Capacitor, Ceramic (MLCC), 4.7nF, ±20%, 1kV, X7R, ±20%, SMD 1206; Manufacturer: HUI JU; Manufacturer Part Number: NV1206B472M102CEDN
footprint CAP-1206 (1206 (3216M) Capacitor)
pins: 1, 2

## NV1206B473K102CEGN
designator C?  Capacitance: 47nF  (hidden comment: *)
Capacitor, Ceramic (MLCC), 47nF, ±10%, 1kV, X7R, ±10%, SMD 1206; Manufacturer: HUI JU; Manufacturer Part Number: NV1206B473K102CEGN
footprint CAP-1206 (1206 (3216M) Capacitor)
pins: 1, 2

## NV1206B561K102CEDN
designator C?  Capacitance: 560pF  (hidden comment: *)
Capacitor, Ceramic (MLCC), 560pF, ±10%, 1kV, X7R, ±10%, SMD 1206; Manufacturer: HUI JU; Manufacturer Part Number: NV1206B561K102CEDN
footprint CAP-1206 (1206 (3216M) Capacitor)
pins: 1, 2

## NV1206B681K102CEDN
designator C?  Capacitance: 680pF  (hidden comment: *)
Capacitor, Ceramic (MLCC), 680pF, ±10%, 1kV, X7R, ±10%, SMD 1206; Manufacturer: HUI JU; Manufacturer Part Number: NV1206B681K102CEDN
footprint CAP-1206 (1206 (3216M) Capacitor)
pins: 1, 2

## SMK316B7102KFHT
designator C?  Capacitance: 1nF  (hidden comment: *)
Capacitor, Ceramic (MLCC), 1nF, ±10%, 630V, X7R, ±10%, SMD 1206; Manufacturer: Taiyo Yuden; Manufacturer Part Number: SMK316B7102KFHT
footprint CAP-1206 (1206 (3216M) Capacitor)
pins: 1, 2

## SMK316B7103KF-T
designator C?  Capacitance: 10nF  (hidden comment: *)
Capacitor, Ceramic (MLCC), 10nF, ±10%, 630V, X7R, ±10%, SMD 1206; Manufacturer: Taiyo Yuden; Manufacturer Part Number: SMK316B7103KF-T
footprint CAP-1206 (1206 (3216M) Capacitor)
pins: 1, 2

## TCC1206COG3R0C500DT
designator C?  Capacitance: 3pF  (hidden comment: *)
Capacitor, Ceramic (MLCC), 3pF, ±0.25pF, 50V, C0G, ±0.25pF, SMD 1206; Manufacturer: CCTC; Manufacturer Part Number: TCC1206COG3R0C500DT
footprint CAP-1206 (1206 (3216M) Capacitor)
pins: 1, 2

## TCC1206COG5R0D500DT
designator C?  Capacitance: 5pF  (hidden comment: *)
Capacitor, Ceramic (MLCC), 5pF, ±0.5pF, 50V, C0G, ±0.5pF, SMD 1206; Manufacturer: CCTC; Manufacturer Part Number: TCC1206COG5R0D500DT
footprint CAP-1206 (1206 (3216M) Capacitor)
pins: 1, 2

## TCC1206COG6R0D500DT
designator C?  Capacitance: 6pF  (hidden comment: *)
Capacitor, Ceramic (MLCC), 6pF, ±0.5pF, 50V, C0G, ±0.5pF, SMD 1206; Manufacturer: CCTC; Manufacturer Part Number: TCC1206COG6R0D500DT
footprint CAP-1206 (1206 (3216M) Capacitor)
pins: 1, 2

## TCC1206COG100J102ET
designator C?  Capacitance: 10pF  (hidden comment: *)
Capacitor, Ceramic (MLCC), 10pF, ±5%, 1kV, C0G, ±5%, SMD 1206; Manufacturer: CCTC; Manufacturer Part Number: TCC1206COG100J102ET
footprint CAP-1206 (1206 (3216M) Capacitor)
pins: 1, 2

## TCC1206COG100J500DT
designator C?  Capacitance: 10pF  (hidden comment: *)
Capacitor, Ceramic (MLCC), 10pF, ±5%, 50V, C0G, ±5%, SMD 1206; Manufacturer: CCTC; Manufacturer Part Number: TCC1206COG100J500DT
footprint CAP-1206 (1206 (3216M) Capacitor)
pins: 1, 2

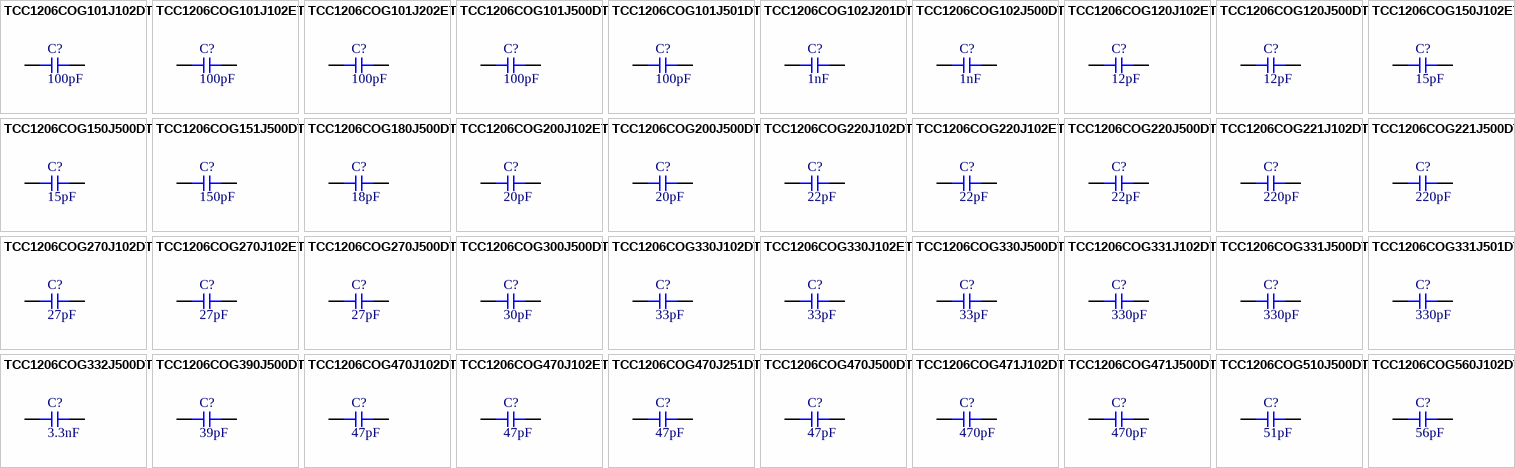
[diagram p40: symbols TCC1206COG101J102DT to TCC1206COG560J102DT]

## TCC1206COG101J102DT
designator C?  Capacitance: 100pF  (hidden comment: *)
Capacitor, Ceramic (MLCC), 100pF, ±5%, 1kV, C0G, ±5%, SMD 1206; Manufacturer: CCTC; Manufacturer Part Number: TCC1206COG101J102DT
footprint CAP-1206 (1206 (3216M) Capacitor)
pins: 1, 2

## TCC1206COG101J102ET
designator C?  Capacitance: 100pF  (hidden comment: *)
Capacitor, Ceramic (MLCC), 100pF, ±5%, 1kV, C0G, ±5%, SMD 1206; Manufacturer: CCTC; Manufacturer Part Number: TCC1206COG101J102ET
footprint CAP-1206 (1206 (3216M) Capacitor)
pins: 1, 2

## TCC1206COG101J202ET
designator C?  Capacitance: 100pF  (hidden comment: *)
Capacitor, Ceramic (MLCC), 100pF, ±5%, 2kV, C0G, ±5%, SMD 1206; Manufacturer: CCTC; Manufacturer Part Number: TCC1206COG101J202ET
footprint CAP-1206 (1206 (3216M) Capacitor)
pins: 1, 2

## TCC1206COG101J500DT
designator C?  Capacitance: 100pF  (hidden comment: *)
Capacitor, Ceramic (MLCC), 100pF, ±5%, 50V, C0G, ±5%, SMD 1206; Manufacturer: CCTC; Manufacturer Part Number: TCC1206COG101J500DT
footprint CAP-1206 (1206 (3216M) Capacitor)
pins: 1, 2

## TCC1206COG101J501DT
designator C?  Capacitance: 100pF  (hidden comment: *)
Capacitor, Ceramic (MLCC), 100pF, ±5%, 500V, C0G, ±5%, SMD 1206; Manufacturer: CCTC; Manufacturer Part Number: TCC1206COG101J501DT
footprint CAP-1206 (1206 (3216M) Capacitor)
pins: 1, 2

## TCC1206COG102J201DT
designator C?  Capacitance: 1nF  (hidden comment: *)
Capacitor, Ceramic (MLCC), 1nF, ±5%, 200V, C0G, ±5%, SMD 1206; Manufacturer: CCTC; Manufacturer Part Number: TCC1206COG102J201DT
footprint CAP-1206 (1206 (3216M) Capacitor)
pins: 1, 2

## TCC1206COG102J500DT
designator C?  Capacitance: 1nF  (hidden comment: *)
Capacitor, Ceramic (MLCC), 1nF, ±5%, 50V, C0G, ±5%, SMD 1206; Manufacturer: CCTC; Manufacturer Part Number: TCC1206COG102J500DT
footprint CAP-1206 (1206 (3216M) Capacitor)
pins: 1, 2

## TCC1206COG120J102ET
designator C?  Capacitance: 12pF  (hidden comment: *)
Capacitor, Ceramic (MLCC), 12pF, ±5%, 1kV, C0G, ±5%, SMD 1206; Manufacturer: CCTC; Manufacturer Part Number: TCC1206COG120J102ET
footprint CAP-1206 (1206 (3216M) Capacitor)
pins: 1, 2

## TCC1206COG120J500DT
designator C?  Capacitance: 12pF  (hidden comment: *)
Capacitor, Ceramic (MLCC), 12pF, ±5%, 50V, C0G, ±5%, SMD 1206; Manufacturer: CCTC; Manufacturer Part Number: TCC1206COG120J500DT
footprint CAP-1206 (1206 (3216M) Capacitor)
pins: 1, 2

## TCC1206COG150J102ET
designator C?  Capacitance: 15pF  (hidden comment: *)
Capacitor, Ceramic (MLCC), 15pF, ±5%, 1kV, C0G, ±5%, SMD 1206; Manufacturer: CCTC; Manufacturer Part Number: TCC1206COG150J102ET
footprint CAP-1206 (1206 (3216M) Capacitor)
pins: 1, 2

## TCC1206COG150J500DT
designator C?  Capacitance: 15pF  (hidden comment: *)
Capacitor, Ceramic (MLCC), 15pF, ±5%, 50V, C0G, ±5%, SMD 1206; Manufacturer: CCTC; Manufacturer Part Number: TCC1206COG150J500DT
footprint CAP-1206 (1206 (3216M) Capacitor)
pins: 1, 2

## TCC1206COG151J500DT
designator C?  Capacitance: 150pF  (hidden comment: *)
Capacitor, Ceramic (MLCC), 150pF, ±5%, 50V, C0G, ±5%, SMD 1206; Manufacturer: CCTC; Manufacturer Part Number: TCC1206COG151J500DT
footprint CAP-1206 (1206 (3216M) Capacitor)
pins: 1, 2

## TCC1206COG180J500DT
designator C?  Capacitance: 18pF  (hidden comment: *)
Capacitor, Ceramic (MLCC), 18pF, ±5%, 50V, C0G, ±5%, SMD 1206; Manufacturer: CCTC; Manufacturer Part Number: TCC1206COG180J500DT
footprint CAP-1206 (1206 (3216M) Capacitor)
pins: 1, 2

## TCC1206COG200J102ET
designator C?  Capacitance: 20pF  (hidden comment: *)
Capacitor, Ceramic (MLCC), 20pF, ±5%, 1kV, C0G, ±5%, SMD 1206; Manufacturer: CCTC; Manufacturer Part Number: TCC1206COG200J102ET
footprint CAP-1206 (1206 (3216M) Capacitor)
pins: 1, 2

## TCC1206COG200J500DT
designator C?  Capacitance: 20pF  (hidden comment: *)
Capacitor, Ceramic (MLCC), 20pF, ±5%, 50V, C0G, ±5%, SMD 1206; Manufacturer: CCTC; Manufacturer Part Number: TCC1206COG200J500DT
footprint CAP-1206 (1206 (3216M) Capacitor)
pins: 1, 2

## TCC1206COG220J102DT
designator C?  Capacitance: 22pF  (hidden comment: *)
Capacitor, Ceramic (MLCC), 22pF, ±5%, 1kV, C0G, ±5%, SMD 1206; Manufacturer: CCTC; Manufacturer Part Number: TCC1206COG220J102DT
footprint CAP-1206 (1206 (3216M) Capacitor)
pins: 1, 2

## TCC1206COG220J102ET
designator C?  Capacitance: 22pF  (hidden comment: *)
Capacitor, Ceramic (MLCC), 22pF, ±5%, 1kV, C0G, ±5%, SMD 1206; Manufacturer: CCTC; Manufacturer Part Number: TCC1206COG220J102ET
footprint CAP-1206 (1206 (3216M) Capacitor)
pins: 1, 2

## TCC1206COG220J500DT
designator C?  Capacitance: 22pF  (hidden comment: *)
Capacitor, Ceramic (MLCC), 22pF, ±5%, 50V, C0G, ±5%, SMD 1206; Manufacturer: CCTC; Manufacturer Part Number: TCC1206COG220J500DT
footprint CAP-1206 (1206 (3216M) Capacitor)
pins: 1, 2

## TCC1206COG221J102DT
designator C?  Capacitance: 220pF  (hidden comment: *)
Capacitor, Ceramic (MLCC), 220pF, ±5%, 1kV, C0G, ±5%, SMD 1206; Manufacturer: CCTC; Manufacturer Part Number: TCC1206COG221J102DT
footprint CAP-1206 (1206 (3216M) Capacitor)
pins: 1, 2

## TCC1206COG221J500DT
designator C?  Capacitance: 220pF  (hidden comment: *)
Capacitor, Ceramic (MLCC), 220pF, ±5%, 50V, C0G, ±5%, SMD 1206; Manufacturer: CCTC; Manufacturer Part Number: TCC1206COG221J500DT
footprint CAP-1206 (1206 (3216M) Capacitor)
pins: 1, 2

## TCC1206COG270J102DT
designator C?  Capacitance: 27pF  (hidden comment: *)
Capacitor, Ceramic (MLCC), 27pF, ±5%, 1kV, C0G, ±5%, SMD 1206; Manufacturer: CCTC; Manufacturer Part Number: TCC1206COG270J102DT
footprint CAP-1206 (1206 (3216M) Capacitor)
pins: 1, 2

## TCC1206COG270J102ET
designator C?  Capacitance: 27pF  (hidden comment: *)
Capacitor, Ceramic (MLCC), 27pF, ±5%, 1kV, C0G, ±5%, SMD 1206; Manufacturer: CCTC; Manufacturer Part Number: TCC1206COG270J102ET
footprint CAP-1206 (1206 (3216M) Capacitor)
pins: 1, 2

## TCC1206COG270J500DT
designator C?  Capacitance: 27pF  (hidden comment: *)
Capacitor, Ceramic (MLCC), 27pF, ±5%, 50V, C0G, ±5%, SMD 1206; Manufacturer: CCTC; Manufacturer Part Number: TCC1206COG270J500DT
footprint CAP-1206 (1206 (3216M) Capacitor)
pins: 1, 2

## TCC1206COG300J500DT
designator C?  Capacitance: 30pF  (hidden comment: *)
Capacitor, Ceramic (MLCC), 30pF, ±5%, 50V, C0G, ±5%, SMD 1206; Manufacturer: CCTC; Manufacturer Part Number: TCC1206COG300J500DT
footprint CAP-1206 (1206 (3216M) Capacitor)
pins: 1, 2

## TCC1206COG330J102DT
designator C?  Capacitance: 33pF  (hidden comment: *)
Capacitor, Ceramic (MLCC), 33pF, ±5%, 1kV, C0G, ±5%, SMD 1206; Manufacturer: CCTC; Manufacturer Part Number: TCC1206COG330J102DT
footprint CAP-1206 (1206 (3216M) Capacitor)
pins: 1, 2

## TCC1206COG330J102ET
designator C?  Capacitance: 33pF  (hidden comment: *)
Capacitor, Ceramic (MLCC), 33pF, ±5%, 1kV, C0G, ±5%, SMD 1206; Manufacturer: CCTC; Manufacturer Part Number: TCC1206COG330J102ET
footprint CAP-1206 (1206 (3216M) Capacitor)
pins: 1, 2

## TCC1206COG330J500DT
designator C?  Capacitance: 33pF  (hidden comment: *)
Capacitor, Ceramic (MLCC), 33pF, ±5%, 50V, C0G, ±5%, SMD 1206; Manufacturer: CCTC; Manufacturer Part Number: TCC1206COG330J500DT
footprint CAP-1206 (1206 (3216M) Capacitor)
pins: 1, 2

## TCC1206COG331J102DT
designator C?  Capacitance: 330pF  (hidden comment: *)
Capacitor, Ceramic (MLCC), 330pF, ±5%, 1kV, C0G, ±5%, SMD 1206; Manufacturer: CCTC; Manufacturer Part Number: TCC1206COG331J102DT
footprint CAP-1206 (1206 (3216M) Capacitor)
pins: 1, 2

## TCC1206COG331J500DT
designator C?  Capacitance: 330pF  (hidden comment: *)
Capacitor, Ceramic (MLCC), 330pF, ±5%, 50V, C0G, ±5%, SMD 1206; Manufacturer: CCTC; Manufacturer Part Number: TCC1206COG331J500DT
footprint CAP-1206 (1206 (3216M) Capacitor)
pins: 1, 2

## TCC1206COG331J501DT
designator C?  Capacitance: 330pF  (hidden comment: *)
Capacitor, Ceramic (MLCC), 330pF, ±5%, 500V, C0G, ±5%, SMD 1206; Manufacturer: CCTC; Manufacturer Part Number: TCC1206COG331J501DT
footprint CAP-1206 (1206 (3216M) Capacitor)
pins: 1, 2

## TCC1206COG332J500DT
designator C?  Capacitance: 3.3nF  (hidden comment: *)
Capacitor, Ceramic (MLCC), 3.3nF, ±5%, 50V, C0G, ±5%, SMD 1206; Manufacturer: CCTC; Manufacturer Part Number: TCC1206COG332J500DT
footprint CAP-1206 (1206 (3216M) Capacitor)
pins: 1, 2

## TCC1206COG390J500DT
designator C?  Capacitance: 39pF  (hidden comment: *)
Capacitor, Ceramic (MLCC), 39pF, ±5%, 50V, C0G, ±5%, SMD 1206; Manufacturer: CCTC; Manufacturer Part Number: TCC1206COG390J500DT
footprint CAP-1206 (1206 (3216M) Capacitor)
pins: 1, 2

## TCC1206COG470J102DT
designator C?  Capacitance: 47pF  (hidden comment: *)
Capacitor, Ceramic (MLCC), 47pF, ±5%, 1kV, C0G, ±5%, SMD 1206; Manufacturer: CCTC; Manufacturer Part Number: TCC1206COG470J102DT
footprint CAP-1206 (1206 (3216M) Capacitor)
pins: 1, 2

## TCC1206COG470J102ET
designator C?  Capacitance: 47pF  (hidden comment: *)
Capacitor, Ceramic (MLCC), 47pF, ±5%, 1kV, C0G, ±5%, SMD 1206; Manufacturer: CCTC; Manufacturer Part Number: TCC1206COG470J102ET
footprint CAP-1206 (1206 (3216M) Capacitor)
pins: 1, 2

## TCC1206COG470J251DT
designator C?  Capacitance: 47pF  (hidden comment: *)
Capacitor, Ceramic (MLCC), 47pF, ±5%, 250V, C0G, ±5%, SMD 1206; Manufacturer: CCTC; Manufacturer Part Number: TCC1206COG470J251DT
footprint CAP-1206 (1206 (3216M) Capacitor)
pins: 1, 2

## TCC1206COG470J500DT
designator C?  Capacitance: 47pF  (hidden comment: *)
Capacitor, Ceramic (MLCC), 47pF, ±5%, 50V, C0G, ±5%, SMD 1206; Manufacturer: CCTC; Manufacturer Part Number: TCC1206COG470J500DT
footprint CAP-1206 (1206 (3216M) Capacitor)
pins: 1, 2

## TCC1206COG471J102DT
designator C?  Capacitance: 470pF  (hidden comment: *)
Capacitor, Ceramic (MLCC), 470pF, ±5%, 1kV, C0G, ±5%, SMD 1206; Manufacturer: CCTC; Manufacturer Part Number: TCC1206COG471J102DT
footprint CAP-1206 (1206 (3216M) Capacitor)
pins: 1, 2

## TCC1206COG471J500DT
designator C?  Capacitance: 470pF  (hidden comment: *)
Capacitor, Ceramic (MLCC), 470pF, ±5%, 50V, C0G, ±5%, SMD 1206; Manufacturer: CCTC; Manufacturer Part Number: TCC1206COG471J500DT
footprint CAP-1206 (1206 (3216M) Capacitor)
pins: 1, 2

## TCC1206COG510J500DT
designator C?  Capacitance: 51pF  (hidden comment: *)
Capacitor, Ceramic (MLCC), 51pF, ±5%, 50V, C0G, ±5%, SMD 1206; Manufacturer: CCTC; Manufacturer Part Number: TCC1206COG510J500DT
footprint CAP-1206 (1206 (3216M) Capacitor)
pins: 1, 2

## TCC1206COG560J102DT
designator C?  Capacitance: 56pF  (hidden comment: *)
Capacitor, Ceramic (MLCC), 56pF, ±5%, 1kV, C0G, ±5%, SMD 1206; Manufacturer: CCTC; Manufacturer Part Number: TCC1206COG560J102DT
footprint CAP-1206 (1206 (3216M) Capacitor)
pins: 1, 2

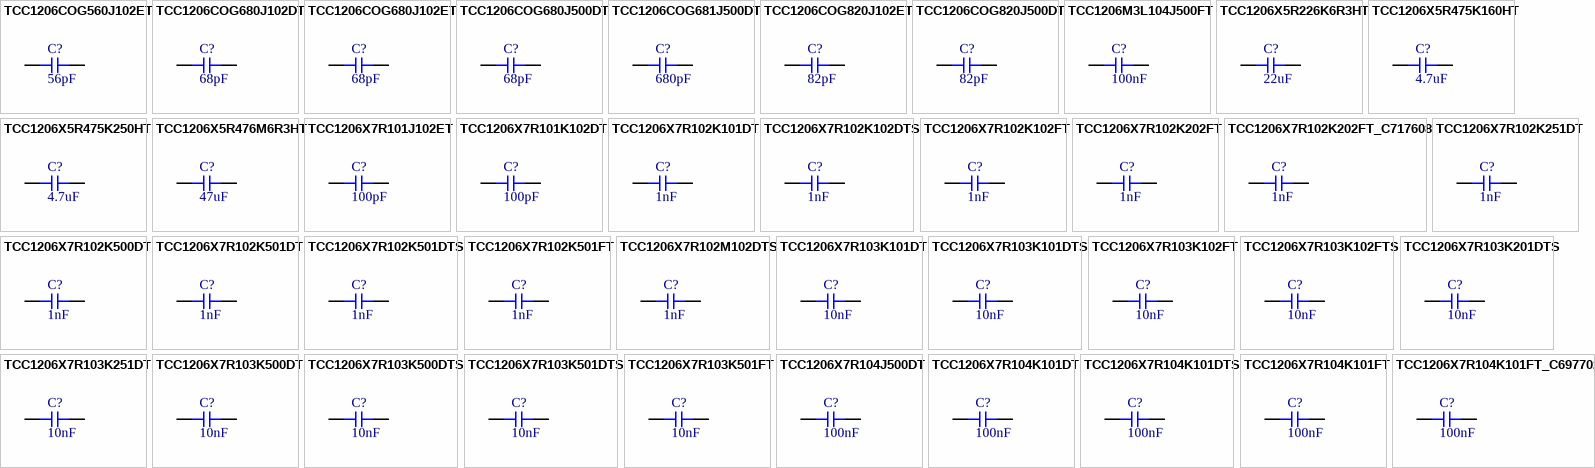
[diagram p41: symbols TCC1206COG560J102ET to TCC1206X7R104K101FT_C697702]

## TCC1206COG560J102ET
designator C?  Capacitance: 56pF  (hidden comment: *)
Capacitor, Ceramic (MLCC), 56pF, ±5%, 1kV, C0G, ±5%, SMD 1206; Manufacturer: CCTC; Manufacturer Part Number: TCC1206COG560J102ET
footprint CAP-1206 (1206 (3216M) Capacitor)
pins: 1, 2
